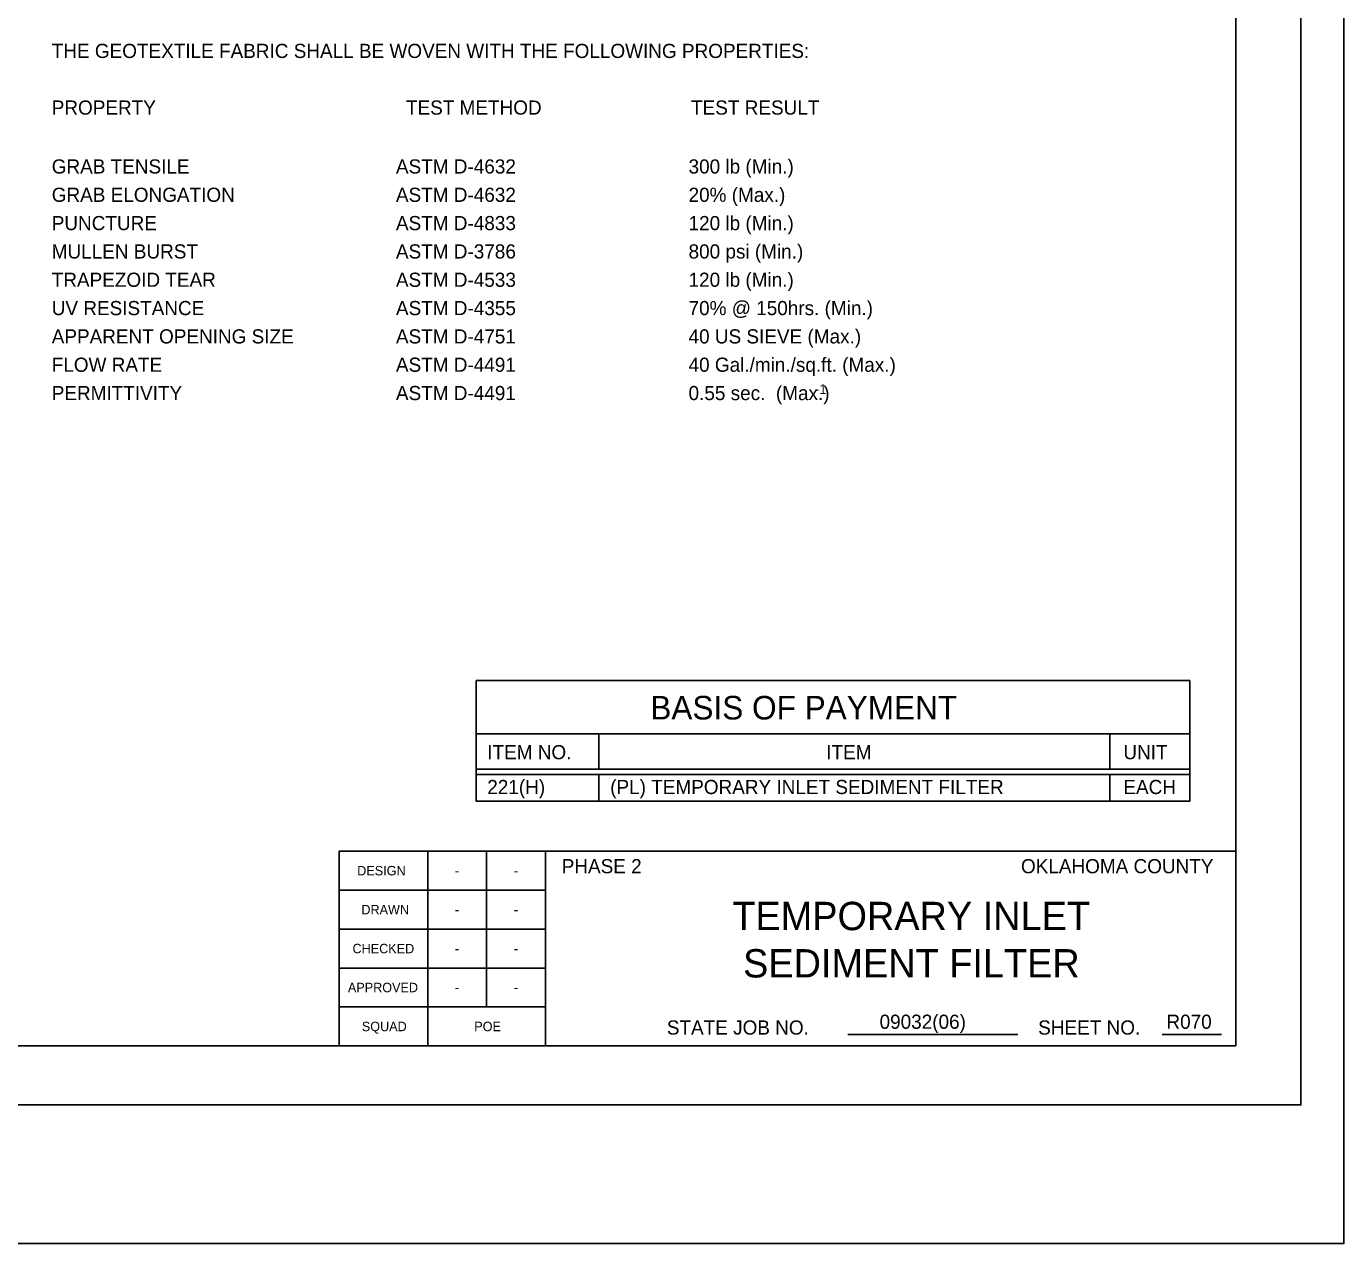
# Model space of a CAD drawing. Extents: x -120.7 to -50.3, y -20.2 to 3.8.
# Drawn here: x -61.42 to -50.26, y -20.24 to -9.93 of the extents above; entities that cross this region are included whole.
import ezdxf

# ---------------------------------------------------------------- set-up
doc = ezdxf.new("R2010")
doc.units = 0
for name, color, linetype in [('SHT_Plot_Shape_Full', 7, 'Continuous'), ('SHT_Plot_Shape_Half', 7, 'Continuous'), ('SHT_Sheet_Border', 7, 'Continuous'), ('SHT_Standard_Sheet_Lines', 7, 'Continuous'), ('SHT_Standard_Sheet_Txt', 7, 'Continuous'), ('TYP_Typical_Section_Linework', 7, 'Continuous'), ('TYP_Typical_Section_Txt', 7, 'Continuous')]:
    doc.layers.add(name, color=color, linetype=linetype)

msp = doc.modelspace()

# ---------------------------------------------------------------- linework, layer by layer
at = {"layer": 'SHT_Plot_Shape_Full'}
msp.add_lwpolyline([(-86.259, 3.759), (-50.259, 3.759), (-50.259, -20.241), (-86.259, -20.241)], close=True, dxfattribs=at)
at = {"layer": 'SHT_Plot_Shape_Half'}
msp.add_lwpolyline([(-84.622, 2.934), (-50.622, 2.934), (-50.622, -19.066), (-84.622, -19.066)], close=True, dxfattribs=at)
at = {"layer": 'SHT_Sheet_Border'}
for p, q in [((-58.772, -18.566), (-58.772, -16.916)), ((-58.772, -16.916), (-51.172, -16.916)), ((-57.022, -18.566), (-57.022, -16.916))]:
    msp.add_line(p, q, dxfattribs=at)
msp.add_lwpolyline([(-51.172, -18.566), (-82.672, -18.566), (-82.672, 2.434), (-51.172, 2.434)], close=True, dxfattribs=at)
at = {"layer": 'SHT_Standard_Sheet_Lines'}
for p, q in [((-58.022, -18.566), (-58.022, -16.916)), ((-57.522, -18.236), (-57.522, -16.916)), ((-54.461, -18.47), (-53.021, -18.47)), ((-51.796, -18.47), (-51.294, -18.47))]:
    msp.add_line(p, q, dxfattribs=at)
for points in [[(-57.022, -17.246), (-58.772, -17.246)], [(-57.022, -17.576), (-58.772, -17.576)], [(-57.022, -17.906), (-58.772, -17.906)], [(-57.022, -18.236), (-58.772, -18.236)]]:
    msp.add_lwpolyline(points, dxfattribs=at)
at = {"layer": 'TYP_Typical_Section_Linework'}
for p, q in [((-57.612, -15.471), (-51.562, -15.471)), ((-57.612, -15.471), (-57.612, -16.491)), ((-51.562, -15.471), (-51.562, -16.491)), ((-57.612, -15.921), (-51.562, -15.921)), ((-56.572, -15.921), (-56.572, -16.221)), ((-52.242, -15.921), (-52.242, -16.221)), ((-57.612, -16.221), (-51.562, -16.221)), ((-57.612, -16.266), (-51.562, -16.266)), ((-56.572, -16.266), (-56.572, -16.491)), ((-52.242, -16.266), (-52.242, -16.491)), ((-57.612, -16.491), (-51.562, -16.491))]:
    msp.add_line(p, q, dxfattribs=at)

# ---------------------------------------------------------------- texts
at = {"layer": 'SHT_Standard_Sheet_Txt'}
for s, height, p in [('DESIGN', 0.08, (-58.619, -17.121)), ('PHASE 2', 0.12, (-56.886, -17.103)), ('OKLAHOMA COUNTY', 0.12, (-52.994, -17.103)), ('-', 0.08, (-57.791, -17.121)), ('-', 0.08, (-57.291, -17.121)), ('DRAWN', 0.08, (-58.584, -17.451)), ('-', 0.08, (-57.791, -17.451)), ('-', 0.08, (-57.291, -17.451)), ('TEMPORARY INLET', 0.24, (-55.44, -17.585)), ('CHECKED', 0.08, (-58.659, -17.781)), ('-', 0.08, (-57.791, -17.781)), ('-', 0.08, (-57.291, -17.781)), ('SEDIMENT FILTER', 0.24, (-55.349, -17.986)), ('APPROVED', 0.08, (-58.698, -18.111)), ('-', 0.08, (-57.791, -18.111)), ('-', 0.08, (-57.291, -18.111)), ('09032(06)', 0.12, (-54.192, -18.421)), ('R070', 0.12, (-51.761, -18.421)), ('SQUAD', 0.08, (-58.58, -18.441)), ('POE', 0.08, (-57.627, -18.441)), ('STATE JOB NO.', 0.12, (-55.995, -18.47)), ('SHEET NO. ', 0.12, (-52.848, -18.47))]:
    msp.add_text(s, height=height, dxfattribs=at).set_placement(p)
at = {"layer": 'TYP_Typical_Section_Txt'}
for s, height, p in [('THE GEOTEXTILE FABRIC SHALL BE WOVEN WITH THE FOLLOWING PROPERTIES:', 0.12, (-61.208, -10.195)), ('PROPERTY', 0.12, (-61.208, -10.675)), ('TEST METHOD', 0.12, (-58.206, -10.675)), ('TEST RESULT', 0.12, (-55.79, -10.675)), ('300 lb (Min.)', 0.12, (-55.811, -11.174)), ('GRAB TENSILE', 0.12, (-61.208, -11.174)), ('ASTM D-4632', 0.12, (-58.291, -11.174)), ('GRAB ELONGATION', 0.12, (-61.208, -11.414)), ('ASTM D-4632', 0.12, (-58.291, -11.414)), ('20% (Max.)', 0.12, (-55.811, -11.414)), ('PUNCTURE', 0.12, (-61.208, -11.654)), ('ASTM D-4833', 0.12, (-58.291, -11.654)), ('120 lb (Min.)', 0.12, (-55.811, -11.654)), ('MULLEN BURST ', 0.12, (-61.208, -11.894)), ('ASTM D-3786', 0.12, (-58.291, -11.894)), ('800 psi (Min.)', 0.12, (-55.811, -11.894)), ('TRAPEZOID TEAR', 0.12, (-61.208, -12.134)), ('ASTM D-4533', 0.12, (-58.291, -12.134)), ('120 lb (Min.)', 0.12, (-55.811, -12.134)), ('UV RESISTANCE', 0.12, (-61.208, -12.374)), ('ASTM D-4355', 0.12, (-58.291, -12.374)), ('70% @ 150hrs. (Min.)', 0.12, (-55.811, -12.374)), ('APPARENT OPENING SIZE', 0.12, (-61.208, -12.614)), ('ASTM D-4751', 0.12, (-58.291, -12.614)), ('40 US SIEVE (Max.)', 0.12, (-55.811, -12.614)), ('FLOW RATE ', 0.12, (-61.208, -12.854)), ('ASTM D-4491', 0.12, (-58.291, -12.854)), ('40 Gal./min./sq.ft. (Max.)', 0.12, (-55.811, -12.854)), ('PERMITTIVITY', 0.12, (-61.208, -13.094)), ('ASTM D-4491', 0.12, (-58.291, -13.094)), ('0.55 sec.  (Max.)', 0.12, (-55.811, -13.094)), ('-1', 0.08, (-54.738, -13.041)), ('BASIS OF PAYMENT', 0.2, (-56.135, -15.8)), ('ITEM NO.', 0.12, (-57.517, -16.137)), ('ITEM', 0.12, (-54.644, -16.137)), ('UNIT', 0.12, (-52.126, -16.137)), ('221(H)', 0.12, (-57.517, -16.432)), ('(PL) TEMPORARY INLET SEDIMENT FILTER', 0.12, (-56.475, -16.432)), ('EACH', 0.12, (-52.126, -16.432))]:
    msp.add_text(s, height=height, dxfattribs=at).set_placement(p)

doc.saveas('drawing.dxf')
